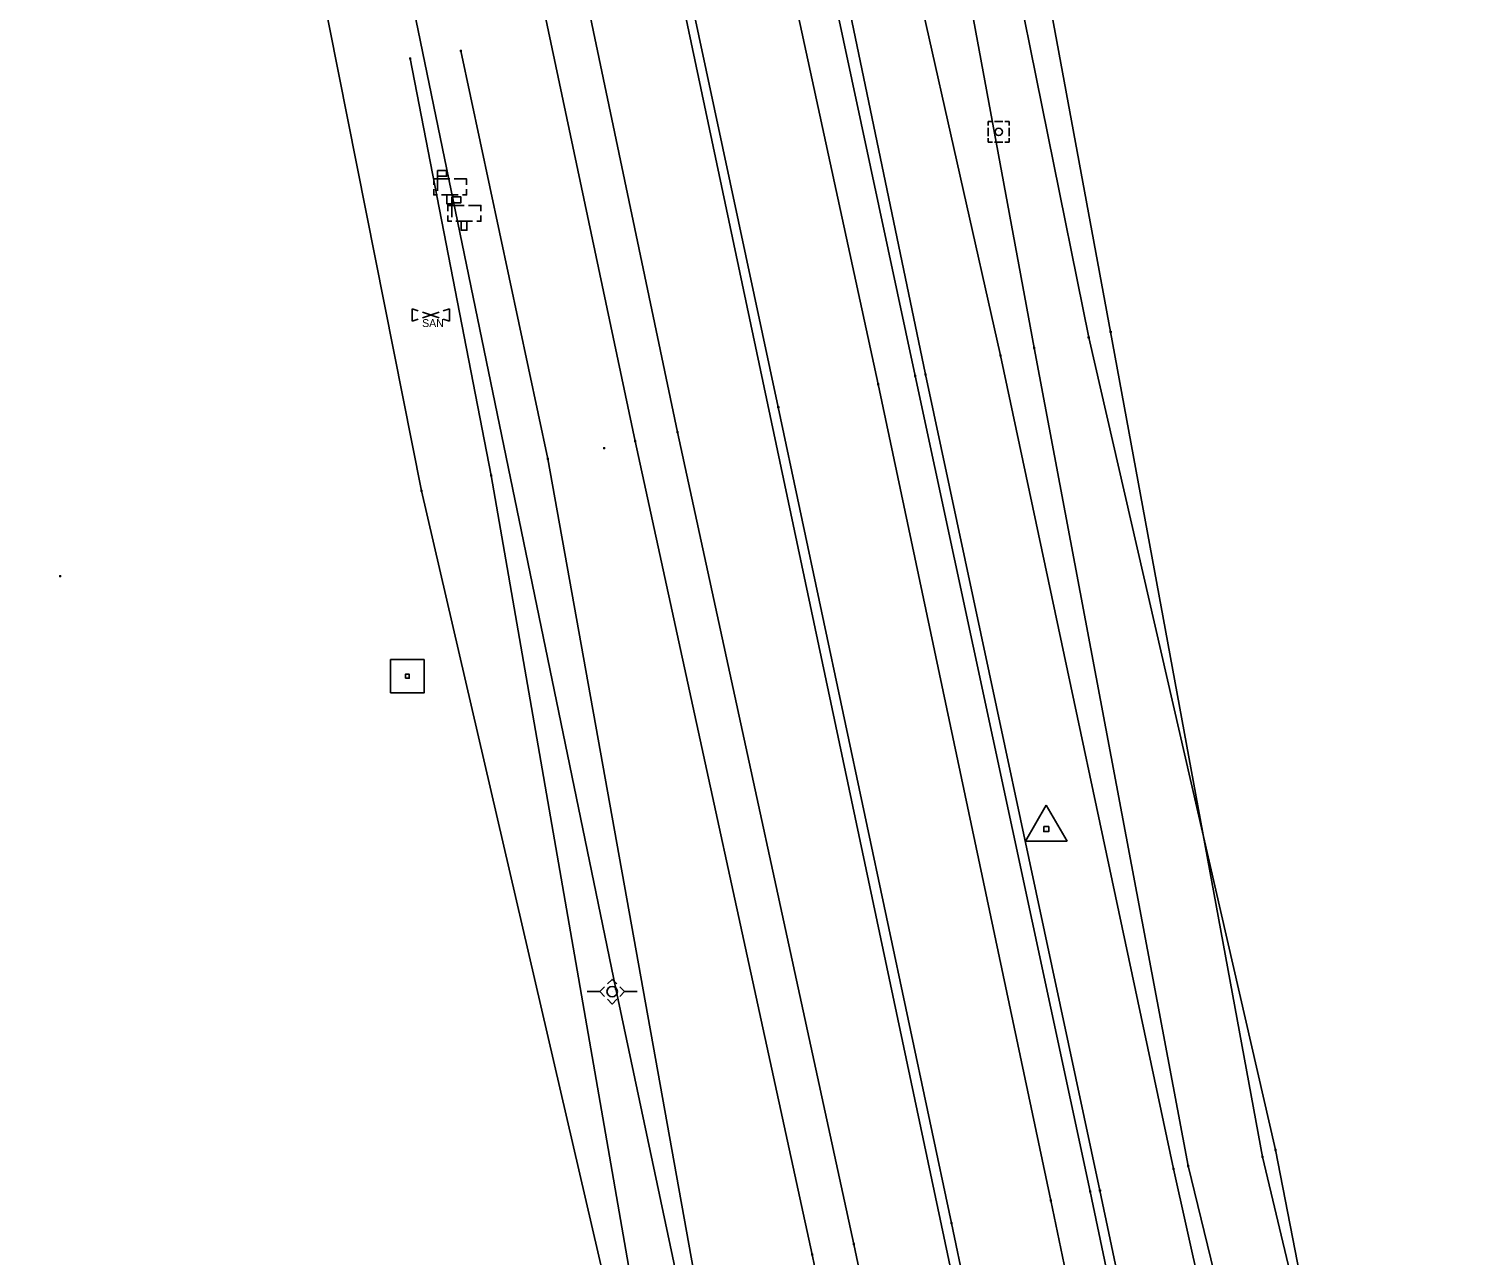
# Model space of a CAD drawing. Extents: x 1954856 to 2011933, y 399149 to 426294.
# Drawn here: x 2005094 to 2005268.6, y 406996.3 to 407143.8 of the extents above; entities that cross this region are included whole.
import ezdxf

# ---------------------------------------------------------------- set-up
doc = ezdxf.new("R2010")
doc.units = 0
for name, color, linetype in [('BankMent_ep', 7, 'Continuous'), ('BaselineSurvey', 7, 'Continuous'), ('ElecAer_ep', 7, 'Continuous'), ('Mailbox_ep', 7, 'Continuous'), ('MonumentCC_ep', 7, 'Continuous'), ('MonumentNL_ep', 7, 'Continuous'), ('PavtAsphalt_ep', 7, 'Continuous'), ('PavtAsphaltCrown_ep', 7, 'Continuous'), ('PointLocator_ep', 7, 'Continuous'), ('PoleShared_ep', 7, 'Continuous'), ('ShldrPaved_ep', 7, 'Continuous'), ('TelePed_ep', 7, 'Continuous'), ('TreeLineWoods_ep', 7, 'Continuous'), ('ValveSewer_ep', 7, 'Continuous')]:
    doc.layers.add(name, color=color, linetype=linetype)

msp = doc.modelspace()

# ---------------------------------------------------------------- linework, layer by layer
at = {"layer": 'BankMent_ep'}
for p, q in [((2005210.69, 407104.54), (2005188.94, 407201.28)), ((2005201.66, 407102.26), (2005181.44, 407199.58)), ((2005149.48, 407090.14), (2005139.77, 407140.23)), ((2005156.31, 407092.13), (2005145.85, 407141.16)), ((2005231.46, 407006.8), (2005210.69, 407104.54)), ((2005222.62, 407004.19), (2005201.66, 407102.26)), ((2005174.06, 406993.05), (2005156.31, 407092.13)), ((2005166.63, 406991.41), (2005149.48, 407090.14)), ((2005253.49, 406908.02), (2005231.46, 407006.8)), ((2005243.23, 406905.78), (2005222.62, 407004.19))]:
    msp.add_line(p, q, dxfattribs=at)
for points in [[(2005309.48, 406680.52), (2005302.97, 406714.33), (2005282.4, 406812.5), (2005263.07, 406909.67), (2005243.71, 407009.06), (2005221.27, 407106.71), (2005201.57, 407204.18), (2005181.73, 407301.56), (2005166.33, 407354.92)], [(2005306.06, 406678.23), (2005296.37, 406713.29), (2005277.07, 406810.93), (2005257.22, 406908.7), (2005233.22, 407007.14), (2005214.71, 407105.45), (2005196.74, 407202.84), (2005177.09, 407300.49), (2005163.81, 407354.47)]]:
    msp.add_lwpolyline(points, dxfattribs=at)
at = {"layer": 'BaselineSurvey'}
msp.add_line((2006223.92, 402174.38), (2005094.48, 407516.05), dxfattribs=at)
msp.add_line((2006223.92, 402174.38), (2005094.48, 407516.05), dxfattribs=at)
at = {"layer": 'ElecAer_ep'}
msp.add_lwpolyline([(2005261.7, 406565.27), (2005211.77, 406805.22), (2005164.45, 407028.42), (2005110.12, 407292.01), (2005075.05, 407240.4), (2005033.12, 407175.89)], dxfattribs=at)
at = {"layer": 'Mailbox_ep'}
for p, q in [((2005143.05, 407124.34), (2005143.05, 407126.08)), ((2005143.05, 407126.08), (2005144.04, 407126.08)), ((2005142.59, 407125.76), (2005142.59, 407125.05)), ((2005144.54, 407125.76), (2005142.59, 407125.76)), ((2005146.54, 407125.76), (2005146.54, 407125.05)), ((2005146.54, 407124.55), (2005146.54, 407123.85)), ((2005143.54, 407123.85), (2005144.04, 407123.85)), ((2005144.04, 407123.85), (2005145.54, 407123.85)), ((2005144.3, 407122.59), (2005144.3, 407121.88)), ((2005146.26, 407122.59), (2005144.3, 407122.59)), ((2005144.52, 407122.77), (2005144.52, 407122.77)), ((2005144.77, 407121.17), (2005144.77, 407122.91)), ((2005144.77, 407122.91), (2005145.76, 407122.91)), ((2005148.26, 407122.59), (2005148.26, 407121.88)), ((2005145.26, 407120.67), (2005145.76, 407120.67)), ((2005145.76, 407120.67), (2005147.26, 407120.67)), ((2005148.26, 407121.38), (2005148.26, 407120.67)), ((2005146.24, 407119.6), (2005146.24, 407119.6))]:
    msp.add_line(p, q, dxfattribs=at)
for points in [[(2005144.04, 407126.77), (2005143.05, 407126.77), (2005143.05, 407126.08)], [(2005144.04, 407126.08), (2005144.13, 407126.08), (2005144.13, 407126.77), (2005144.04, 407126.77)], [(2005142.48, 407125.89), (2005142.56, 407125.89), (2005142.59, 407125.71)], [(2005142.59, 407124.55), (2005142.59, 407123.85), (2005143.04, 407123.85)], [(2005146.54, 407125.3), (2005146.54, 407125.76), (2005145.04, 407125.76)], [(2005146.04, 407123.85), (2005146.54, 407123.85), (2005146.54, 407124.3)], [(2005144.18, 407123.85), (2005144.18, 407122.77), (2005144.87, 407122.77), (2005144.87, 407123.85)], [(2005144.19, 407122.72), (2005144.27, 407122.72), (2005144.3, 407122.54)], [(2005145.76, 407123.6), (2005144.77, 407123.6), (2005144.77, 407122.91)], [(2005145.76, 407122.91), (2005145.85, 407122.91), (2005145.85, 407123.6), (2005145.76, 407123.6)], [(2005148.26, 407122.13), (2005148.26, 407122.59), (2005146.76, 407122.59)], [(2005144.3, 407121.38), (2005144.3, 407120.67), (2005144.76, 407120.67)], [(2005145.9, 407120.67), (2005145.9, 407119.6), (2005146.58, 407119.6), (2005146.58, 407120.67)], [(2005147.76, 407120.67), (2005148.26, 407120.67), (2005148.26, 407121.13)]]:
    msp.add_lwpolyline(points, dxfattribs=at)
at = {"layer": 'MonumentCC_ep'}
msp.add_line((2005139.41, 407066), (2005139.41, 407066), dxfattribs=at)
msp.add_lwpolyline([(2005137.41, 407064), (2005141.42, 407064), (2005141.42, 407068), (2005137.41, 407068), (2005137.41, 407064)], dxfattribs=at)
msp.add_lwpolyline([(2005139.18, 407065.76), (2005139.18, 407066.23), (2005139.65, 407066.23), (2005139.65, 407065.76)], close=True, dxfattribs=at)
at = {"layer": 'MonumentNL_ep'}
for p, q in [((2005213.67, 407046.19), (2005216.17, 407050.52)), ((2005216.17, 407050.52), (2005218.67, 407046.19)), ((2005216.17, 407047.63), (2005216.17, 407047.63)), ((2005213.67, 407046.19), (2005218.67, 407046.19))]:
    msp.add_line(p, q, dxfattribs=at)
msp.add_lwpolyline([(2005215.87, 407047.93), (2005216.47, 407047.93), (2005216.47, 407047.33), (2005215.87, 407047.33)], close=True, dxfattribs=at)
at = {"layer": 'PavtAsphalt_ep'}
for p, q in [((2005195.99, 407101.08), (2005174.9, 407198.44)), ((2005171.88, 407095.33), (2005151.27, 407193.74)), ((2005216.72, 407002.99), (2005195.99, 407101.08)), ((2005193.06, 406997.76), (2005171.88, 407095.33)), ((2005237.16, 406904.57), (2005216.72, 407002.99)), ((2005213.39, 406900.36), (2005193.06, 406997.76))]:
    msp.add_line(p, q, dxfattribs=at)
at = {"layer": 'PavtAsphaltCrown_ep'}
for p, q in [((2005183.98, 407098.33), (2005163.1, 407196.11)), ((2005204.8, 407000.25), (2005183.98, 407098.33)), ((2005225.22, 406902.53), (2005204.8, 407000.25))]:
    msp.add_line(p, q, dxfattribs=at)
at = {"layer": 'PointLocator_ep'}
for p, q in [((2005139.89, 407140.23), (2005139.64, 407140.23)), ((2005139.77, 407140.11), (2005139.77, 407140.36)), ((2005139.77, 407140.23), (2005139.77, 407140.23)), ((2005145.97, 407141.16), (2005145.72, 407141.16)), ((2005145.85, 407141.03), (2005145.85, 407141.28)), ((2005145.85, 407141.16), (2005145.85, 407141.16)), ((2005221.39, 407106.71), (2005221.14, 407106.71)), ((2005221.27, 407106.59), (2005221.27, 407106.84)), ((2005221.27, 407106.71), (2005221.27, 407106.71)), ((2005224.03, 407107.37), (2005223.78, 407107.37)), ((2005223.9, 407107.25), (2005223.9, 407107.5)), ((2005223.9, 407107.37), (2005223.9, 407107.37)), ((2005214.84, 407105.45), (2005214.59, 407105.45)), ((2005214.71, 407105.32), (2005214.71, 407105.57)), ((2005214.71, 407105.45), (2005214.71, 407105.45)), ((2005210.81, 407104.54), (2005210.56, 407104.54)), ((2005210.69, 407104.42), (2005210.69, 407104.67)), ((2005210.69, 407104.54), (2005210.69, 407104.54)), ((2005200.54, 407102.08), (2005200.29, 407102.08)), ((2005200.41, 407101.95), (2005200.41, 407102.2)), ((2005200.41, 407102.08), (2005200.41, 407102.08)), ((2005201.78, 407102.26), (2005201.53, 407102.26)), ((2005201.66, 407102.14), (2005201.66, 407102.39)), ((2005201.66, 407102.26), (2005201.66, 407102.26)), ((2005196.11, 407101.08), (2005195.86, 407101.08)), ((2005195.99, 407100.95), (2005195.99, 407101.2)), ((2005195.99, 407101.08), (2005195.99, 407101.08)), ((2005184.11, 407098.33), (2005183.86, 407098.33)), ((2005183.98, 407098.2), (2005183.98, 407098.45)), ((2005183.98, 407098.33), (2005183.98, 407098.33)), ((2005172, 407095.33), (2005171.75, 407095.33)), ((2005171.88, 407095.21), (2005171.88, 407095.46)), ((2005171.88, 407095.33), (2005171.88, 407095.33)), ((2005163.18, 407093.39), (2005162.93, 407093.39)), ((2005163.06, 407093.27), (2005163.06, 407093.52)), ((2005163.06, 407093.39), (2005163.06, 407093.39)), ((2005166.92, 407094.24), (2005166.67, 407094.24)), ((2005166.79, 407094.11), (2005166.79, 407094.36)), ((2005166.79, 407094.24), (2005166.79, 407094.24)), ((2005156.43, 407092.13), (2005156.18, 407092.13)), ((2005156.31, 407092), (2005156.31, 407092.25)), ((2005156.31, 407092.13), (2005156.31, 407092.13)), ((2005149.61, 407090.14), (2005149.36, 407090.14)), ((2005149.48, 407090.01), (2005149.48, 407090.26)), ((2005149.48, 407090.14), (2005149.48, 407090.14)), ((2005141.25, 407088.27), (2005141, 407088.27)), ((2005141.12, 407088.14), (2005141.12, 407088.39)), ((2005141.12, 407088.27), (2005141.12, 407088.27)), ((2005097.83, 407078.03), (2005097.58, 407078.03)), ((2005097.7, 407077.9), (2005097.7, 407078.15)), ((2005097.7, 407078.03), (2005097.7, 407078.03)), ((2005164.58, 407028.42), (2005164.33, 407028.42)), ((2005164.45, 407028.3), (2005164.45, 407028.55)), ((2005164.45, 407028.42), (2005164.45, 407028.42)), ((2005243.83, 407009.06), (2005243.58, 407009.06)), ((2005243.71, 407008.93), (2005243.71, 407009.18)), ((2005243.71, 407009.06), (2005243.71, 407009.06)), ((2005233.22, 407007.01), (2005233.22, 407007.26)), ((2005242.26, 407008.24), (2005242.01, 407008.24)), ((2005242.13, 407008.12), (2005242.13, 407008.37)), ((2005242.13, 407008.24), (2005242.13, 407008.24)), ((2005231.58, 407006.8), (2005231.33, 407006.8)), ((2005231.46, 407006.68), (2005231.46, 407006.93)), ((2005231.46, 407006.8), (2005231.46, 407006.8)), ((2005233.35, 407007.14), (2005233.1, 407007.14)), ((2005233.22, 407007.14), (2005233.22, 407007.14)), ((2005221.57, 407004.07), (2005221.32, 407004.07)), ((2005221.45, 407003.95), (2005221.45, 407004.2)), ((2005221.45, 407004.07), (2005221.45, 407004.07)), ((2005222.75, 407004.19), (2005222.5, 407004.19)), ((2005222.62, 407004.06), (2005222.62, 407004.31)), ((2005222.62, 407004.19), (2005222.62, 407004.19)), ((2005216.84, 407002.99), (2005216.59, 407002.99)), ((2005216.72, 407002.86), (2005216.72, 407003.11)), ((2005216.72, 407002.99), (2005216.72, 407002.99)), ((2005204.92, 407000.25), (2005204.67, 407000.25)), ((2005204.8, 407000.13), (2005204.8, 407000.38)), ((2005204.8, 407000.25), (2005204.8, 407000.25)), ((2005193.18, 406997.76), (2005192.93, 406997.76)), ((2005193.06, 406997.64), (2005193.06, 406997.89)), ((2005193.06, 406997.76), (2005193.06, 406997.76)), ((2005188.17, 406996.51), (2005187.92, 406996.51)), ((2005188.04, 406996.38), (2005188.04, 406996.63)), ((2005188.04, 406996.51), (2005188.04, 406996.51))]:
    msp.add_line(p, q, dxfattribs=at)
at = {"layer": 'PoleShared_ep'}
for p, q in [((2005162.53, 407028.09), (2005163.1, 407028.65)), ((2005161.03, 407028.09), (2005162.53, 407028.09)), ((2005163.09, 407027.52), (2005162.53, 407028.09)), ((2005164.02, 407028.09), (2005164.02, 407028.09)), ((2005167.01, 407028.09), (2005165.51, 407028.09))]:
    msp.add_line(p, q, dxfattribs=at)
for points in [[(2005163.45, 407029.01), (2005164.02, 407029.57), (2005164.58, 407029.01)], [(2005164.94, 407028.65), (2005165.51, 407028.09), (2005164.94, 407027.52)], [(2005164.59, 407027.17), (2005164.02, 407026.6), (2005163.45, 407027.17)]]:
    msp.add_lwpolyline(points, dxfattribs=at)
for start, end in [(90, 270), (270, 90)]:
    msp.add_arc((2005164.02, 407028.09), 0.625, start, end, dxfattribs=at)
at = {"layer": 'ShldrPaved_ep'}
for p, q in [((2005200.41, 407102.08), (2005179.68, 407199.37)), ((2005166.79, 407094.24), (2005153.13, 407158.87)), ((2005221.45, 407004.07), (2005200.41, 407102.08)), ((2005188.04, 406996.51), (2005166.79, 407094.24)), ((2005242.11, 406905.6), (2005221.45, 407004.07)), ((2005208.4, 406899.51), (2005188.04, 406996.51))]:
    msp.add_line(p, q, dxfattribs=at)
at = {"layer": 'TelePed_ep'}
for p, q in [((2005209.21, 407132.67), (2005209.71, 407132.67)), ((2005209.21, 407132.17), (2005209.21, 407132.67)), ((2005209.21, 407130.92), (2005209.21, 407131.92)), ((2005209.96, 407132.67), (2005210.96, 407132.67)), ((2005210.46, 407131.42), (2005210.46, 407131.42)), ((2005211.21, 407132.67), (2005211.71, 407132.67)), ((2005211.71, 407132.17), (2005211.71, 407132.67)), ((2005211.71, 407130.92), (2005211.71, 407131.92)), ((2005209.21, 407130.17), (2005209.21, 407130.67)), ((2005209.71, 407130.17), (2005209.21, 407130.17)), ((2005210.96, 407130.17), (2005209.96, 407130.17)), ((2005211.71, 407130.17), (2005211.21, 407130.17)), ((2005211.71, 407130.17), (2005211.71, 407130.67))]:
    msp.add_line(p, q, dxfattribs=at)
msp.add_circle((2005210.46, 407131.42), 0.438, dxfattribs=at)
at = {"layer": 'TreeLineWoods_ep'}
for points in [[(2005396.16, 406442.29), (2005348.96, 406489.45), (2005344.65, 406519.64), (2005321.38, 406616.19), (2005301.57, 406714.44), (2005284.12, 406812.99), (2005265.54, 406910.08), (2005242.13, 407008.24), (2005223.9, 407107.37), (2005205.9, 407204.74), (2005185.1, 407302.14), (2005170.72, 407356.46), (2005205.33, 407355.25)], [(2005114.03, 406671.84), (2005228.71, 406714.83), (2005204.69, 406796.01), (2005184, 406894.69), (2005163.82, 406990.27), (2005141.12, 407088.27), (2005126.72, 407160.96)]]:
    msp.add_lwpolyline(points, dxfattribs=at)
at = {"layer": 'ValveSewer_ep'}
for p, q in [((2005140.73, 407109.9), (2005139.98, 407110.15)), ((2005139.98, 407108.66), (2005139.98, 407110.15)), ((2005139.98, 407108.66), (2005140.73, 407108.91)), ((2005143.23, 407109.07), (2005141.23, 407109.74)), ((2005141.23, 407109.07), (2005143.23, 407109.74)), ((2005142.23, 407109.41), (2005142.23, 407109.41)), ((2005143.73, 407109.9), (2005144.48, 407110.15)), ((2005144.48, 407108.66), (2005143.73, 407108.91)), ((2005144.48, 407110.15), (2005144.48, 407108.66))]:
    msp.add_line(p, q, dxfattribs=at)

# ---------------------------------------------------------------- texts
msp.add_text('SAN', height=0.95, dxfattribs=at).set_placement((2005141.19, 407107.96))

doc.saveas('drawing.dxf')
